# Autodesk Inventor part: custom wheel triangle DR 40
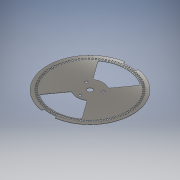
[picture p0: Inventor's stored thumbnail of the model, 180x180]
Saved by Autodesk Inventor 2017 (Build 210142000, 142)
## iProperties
Created: 2016-09
Part Number: custom wheel triangle DR 40
Material: Generic
Document SubType Name: Modeling
Designer: Radek
Density: 1 g/cm^3
Appearance: Mirror
Author: Radek
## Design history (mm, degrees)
workplane "Work Plane1"
sketch "Sketch1"
  geometry: L1 (-46.781, 4.422)-(-44.253, 4.183) reference; L2 (-44.362, 2.791)-(-46.897, 2.951) reference; L3 (-46.411, 7.351)-(-43.903, 6.954) reference; L4 (-44.099, 5.571)-(-46.619, 5.889) reference; L5 (-45.858, 10.251)-(-43.38, 9.696) reference; L6 (-43.663, 8.329)-(-46.158, 8.805) reference; L7 (-45.124, 13.11)-(-42.685, 12.401) reference; L8 (-43.054, 11.054)-(-45.514, 11.686) reference; L9 (-44.212, 15.917)-(-41.822, 15.057) reference; L10 (-42.274, 13.736)-(-44.69, 14.521) reference; L11 (-43.125, 18.662)-(-40.794, 17.653) reference; L12 (-41.329, 16.363)-(-43.69, 17.298) reference; L13 (-41.868, 21.333)-(-39.605, 20.18) reference; L14 (-40.22, 18.926)-(-42.518, 20.007) reference; L15 (-40.446, 23.92)-(-38.26, 22.627) reference; L16 (-38.952, 21.414)-(-41.178, 22.638) reference; L17 (-38.865, 26.412)-(-36.764, 24.985) reference; L18 (-37.53, 23.818)-(-39.675, 25.179) reference; L19 (-37.129, 28.801)-(-35.122, 27.244) reference; L20 (-35.961, 26.127)-(-38.016, 27.62) reference; L21 (-35.248, 31.075)-(-33.342, 29.395) reference; L22 (-34.249, 28.333)-(-36.206, 29.953) reference; L23 (-33.227, 33.227)-(-31.431, 31.431) reference; L24 (-32.403, 30.428)-(-34.254, 32.167) reference; L25 (-31.075, 35.248)-(-29.395, 33.342) reference; L26 (-30.428, 32.403)-(-32.167, 34.254) reference; L27 (-28.801, 37.129)-(-27.244, 35.122) reference; L28 (-28.333, 34.249)-(-29.953, 36.206) reference; L29 (-26.412, 38.865)-(-24.985, 36.764) reference; L30 (-26.127, 35.961)-(-27.62, 38.016) reference; L31 (-23.92, 40.446)-(-22.627, 38.26) reference; L32 (-23.818, 37.53)-(-25.179, 39.675) reference; L33 (-21.333, 41.868)-(-20.18, 39.605) reference; L34 (-21.414, 38.952)-(-22.638, 41.178) reference; L35 (-18.662, 43.125)-(-17.653, 40.794) reference; L36 (-18.926, 40.22)-(-20.007, 42.518) reference; L37 (-15.917, 44.212)-(-15.057, 41.822) reference; L38 (-16.363, 41.329)-(-17.298, 43.69) reference; L39 (-13.11, 45.124)-(-12.401, 42.685) reference; L40 (-13.736, 42.274)-(-14.521, 44.69) reference; L41 (-10.251, 45.858)-(-9.696, 43.38) reference; L42 (-11.054, 43.054)-(-11.686, 45.514) reference; L43 (-7.351, 46.411)-(-6.954, 43.903) reference; L44 (-8.329, 43.663)-(-8.805, 46.158) reference; L45 (-4.422, 46.781)-(-4.183, 44.253) reference; L46 (-5.571, 44.099)-(-5.889, 46.619) reference; L47 (-1.476, 46.967)-(-1.396, 44.428) reference; L48 (-2.791, 44.362)-(-2.951, 46.897) reference; L49 (1.476, 46.967)-(1.396, 44.428) reference; L50 (0, 44.45)-(0, 46.99) reference; L51 (4.422, 46.781)-(4.183, 44.253) reference; L52 (2.791, 44.362)-(2.951, 46.897) reference; L53 (7.351, 46.411)-(6.954, 43.903) reference; L54 (5.571, 44.099)-(5.889, 46.619) reference; L55 (10.251, 45.858)-(9.696, 43.38) reference; L56 (8.329, 43.663)-(8.805, 46.158) reference; L57 (13.11, 45.124)-(12.401, 42.685) reference; L58 (11.054, 43.054)-(11.686, 45.514) reference; L59 (15.917, 44.212)-(15.057, 41.822) reference; L60 (13.736, 42.274)-(14.521, 44.69) reference; L61 (18.662, 43.125)-(17.653, 40.794) reference; L62 (16.363, 41.329)-(17.298, 43.69) reference; L63 (21.333, 41.868)-(20.18, 39.605) reference; L64 (18.926, 40.22)-(20.007, 42.518) reference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; C1 r 50.8 at (0, 0) reference; C2 r 2.984 at (0, 0) reference; C3 r 1.524 at (0, 6.553) reference; C4 r 1.524 at (10.339, 5.969) reference; C5 r 2.984 at (0, 0) reference; C6 r 1.524 at (0, -11.938) reference; C7 r 1.524 at (-5.675, -3.277) reference; C8 r 1.524 at (-10.339, 5.969) reference; C9 r 1.524 at (5.675, -3.277) reference; C10 r 50.8 at (0, 0) reference; C11 r 1.524 at (-5.675, -3.277) reference; C12 r 1.524 at (-10.339, 5.969) reference; C13 r 1.524 at (0, 6.553) reference; C14 r 1.524 at (10.339, 5.969) reference; C15 r 1.524 at (5.675, -3.277) reference; C16 r 1.524 at (0, -11.938) reference; C17 r 2.984 at (0, 0) reference; A1 r 17.081 centre (0, 0) between (0, -17.081) and (17.081, 0) reference; A2 r 17.081 centre (0, 0) between (0, 17.081) and (-17.081, 0) reference; A3 r 43.18 centre (0, 0) between (0, 43.18) and (-43.18, 0) reference; A4 r 43.18 centre (0, 0) between (0, -43.18) and (43.18, 0) reference; A5 r 44.45 centre (0, 0) between (-44.253, 4.183) and (-44.362, 2.791) reference; A6 r 46.99 centre (0, 0) between (-46.781, 4.422) and (-46.897, 2.951) reference; A7 r 44.45 centre (0, 0) between (-43.903, 6.954) and (-44.099, 5.571) reference; A8 r 46.99 centre (0, 0) between (-46.411, 7.351) and (-46.619, 5.889) reference; A9 r 44.45 centre (0, 0) between (-43.38, 9.696) and (-43.663, 8.329) reference; A10 r 46.99 centre (0, 0) between (-45.858, 10.251) and (-46.158, 8.805) reference; A11 r 44.45 centre (0, 0) between (-42.685, 12.401) and (-43.054, 11.054) reference; A12 r 46.99 centre (0, 0) between (-45.124, 13.11) and (-45.514, 11.686) reference; A13 r 44.45 centre (0, 0) between (-41.822, 15.057) and (-42.274, 13.736) reference; A14 r 46.99 centre (0, 0) between (-44.212, 15.917) and (-44.69, 14.521) reference; A15 r 44.45 centre (0, 0) between (-40.794, 17.653) and (-41.329, 16.363) reference; A16 r 46.99 centre (0, 0) between (-43.125, 18.662) and (-43.69, 17.298) reference; A17 r 44.45 centre (0, 0) between (-39.605, 20.18) and (-40.22, 18.926) reference; A18 r 46.99 centre (0, 0) between (-41.868, 21.333) and (-42.518, 20.007) reference; A19 r 44.45 centre (0, 0) between (-38.26, 22.627) and (-38.952, 21.414) reference; A20 r 46.99 centre (0, 0) between (-40.446, 23.92) and (-41.178, 22.638) reference; A21 r 44.45 centre (0, 0) between (-36.764, 24.985) and (-37.53, 23.818) reference; A22 r 46.99 centre (0, 0) between (-38.865, 26.412) and (-39.675, 25.179) reference; A23 r 44.45 centre (0, 0) between (-35.122, 27.244) and (-35.961, 26.127) reference; A24 r 46.99 centre (0, 0) between (-37.129, 28.801) and (-38.016, 27.62) reference; A25 r 44.45 centre (0, 0) between (-33.342, 29.395) and (-34.249, 28.333) reference; A26 r 46.99 centre (0, 0) between (-35.248, 31.075) and (-36.206, 29.953) reference; A27 r 44.45 centre (0, 0) between (-31.431, 31.431) and (-32.403, 30.428) reference; A28 r 46.99 centre (0, 0) between (-33.227, 33.227) and (-34.254, 32.167) reference; A29 r 44.45 centre (0, 0) between (-29.395, 33.342) and (-30.428, 32.403) reference; A30 r 46.99 centre (0, 0) between (-31.075, 35.248) and (-32.167, 34.254) reference; A31 r 44.45 centre (0, 0) between (-27.244, 35.122) and (-28.333, 34.249) reference; A32 r 46.99 centre (0, 0) between (-28.801, 37.129) and (-29.953, 36.206) reference; A33 r 44.45 centre (0, 0) between (-24.985, 36.764) and (-26.127, 35.961) reference; A34 r 46.99 centre (0, 0) between (-26.412, 38.865) and (-27.62, 38.016) reference; A35 r 44.45 centre (0, 0) between (-22.627, 38.26) and (-23.818, 37.53) reference; A36 r 46.99 centre (0, 0) between (-23.92, 40.446) and (-25.179, 39.675) reference; A37 r 44.45 centre (0, 0) between (-20.18, 39.605) and (-21.414, 38.952) reference; A38 r 46.99 centre (0, 0) between (-21.333, 41.868) and (-22.638, 41.178) reference; A39 r 44.45 centre (0, 0) between (-17.653, 40.794) and (-18.926, 40.22) reference; A40 r 46.99 centre (0, 0) between (-18.662, 43.125) and (-20.007, 42.518) reference; A41 r 44.45 centre (0, 0) between (-15.057, 41.822) and (-16.363, 41.329) reference; A42 r 46.99 centre (0, 0) between (-15.917, 44.212) and (-17.298, 43.69) reference; A43 r 44.45 centre (0, 0) between (-12.401, 42.685) and (-13.736, 42.274) reference; A44 r 46.99 centre (0, 0) between (-13.11, 45.124) and (-14.521, 44.69) reference; A45 r 44.45 centre (0, 0) between (-9.696, 43.38) and (-11.054, 43.054) reference; A46 r 46.99 centre (0, 0) between (-10.251, 45.858) and (-11.686, 45.514) reference; A47 r 44.45 centre (0, 0) between (-6.954, 43.903) and (-8.329, 43.663) reference; A48 r 46.99 centre (0, 0) between (-7.351, 46.411) and (-8.805, 46.158) reference; A49 r 44.45 centre (0, 0) between (-4.183, 44.253) and (-5.571, 44.099) reference; A50 r 46.99 centre (0, 0) between (-4.422, 46.781) and (-5.889, 46.619) reference; A51 r 44.45 centre (0, 0) between (-1.396, 44.428) and (-2.791, 44.362) reference; A52 r 46.99 centre (0, 0) between (-1.476, 46.967) and (-2.951, 46.897) reference; A53 r 44.45 centre (0, 0) between (1.396, 44.428) and (0, 44.45) reference; A54 r 46.99 centre (0, 0) between (1.476, 46.967) and (0, 46.99) reference; A55 r 44.45 centre (0, 0) between (4.183, 44.253) and (2.791, 44.362) reference; A56 r 46.99 centre (0, 0) between (4.422, 46.781) and (2.951, 46.897) reference; A57 r 44.45 centre (0, 0) between (6.954, 43.903) and (5.571, 44.099) reference; A58 r 46.99 centre (0, 0) between (7.351, 46.411) and (5.889, 46.619) reference; A59 r 44.45 centre (0, 0) between (9.696, 43.38) and (8.329, 43.663) reference; A60 r 46.99 centre (0, 0) between (10.251, 45.858) and (8.805, 46.158) reference; A61 r 44.45 centre (0, 0) between (12.401, 42.685) and (11.054, 43.054) reference; A62 r 46.99 centre (0, 0) between (13.11, 45.124) and (11.686, 45.514) reference; A63 r 44.45 centre (0, 0) between (15.057, 41.822) and (13.736, 42.274) reference; A64 r 46.99 centre (0, 0) between (15.917, 44.212) and (14.521, 44.69) reference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; 1 further point
  constraints: 8 end point, 2 collinear, 1 parallel
extrude "Extrusion2" new body sketch "Sketch1" distance "d2" = 0.3; taper "d3" = 0 deg
sketch "Sketch2"
  geometry: L1 (-46.781, 4.422)-(-44.253, 4.183) reference; L2 (-44.362, 2.791)-(-46.897, 2.951) reference; L3 (-46.411, 7.351)-(-43.903, 6.954) reference; L4 (-44.099, 5.571)-(-46.619, 5.889) reference; L5 (-45.858, 10.251)-(-43.38, 9.696) reference; L6 (-43.663, 8.329)-(-46.158, 8.805) reference; L7 (-45.124, 13.11)-(-42.685, 12.401) reference; L8 (-43.054, 11.054)-(-45.514, 11.686) reference; L9 (-44.212, 15.917)-(-41.822, 15.057) reference; L10 (-42.274, 13.736)-(-44.69, 14.521) reference; L11 (-43.125, 18.662)-(-40.794, 17.653) reference; L12 (-41.329, 16.363)-(-43.69, 17.298) reference; L13 (-41.868, 21.333)-(-39.605, 20.18) reference; L14 (-40.22, 18.926)-(-42.518, 20.007) reference; L15 (-40.446, 23.92)-(-38.26, 22.627) reference; L16 (-38.952, 21.414)-(-41.178, 22.638) reference; L17 (-38.865, 26.412)-(-36.764, 24.985) reference; L18 (-37.53, 23.818)-(-39.675, 25.179) reference; L19 (-37.129, 28.801)-(-35.122, 27.244) reference; L20 (-35.961, 26.127)-(-38.016, 27.62) reference; L21 (-35.248, 31.075)-(-33.342, 29.395) reference; L22 (-34.249, 28.333)-(-36.206, 29.953) reference; L23 (-33.227, 33.227)-(-31.431, 31.431) reference; L24 (-32.403, 30.428)-(-34.254, 32.167) reference; L25 (-31.075, 35.248)-(-29.395, 33.342) reference; L26 (-30.428, 32.403)-(-32.167, 34.254) reference; L27 (-28.801, 37.129)-(-27.244, 35.122) reference; L28 (-28.333, 34.249)-(-29.953, 36.206) reference; L29 (-26.412, 38.865)-(-24.985, 36.764) reference; L30 (-26.127, 35.961)-(-27.62, 38.016) reference; L31 (-23.92, 40.446)-(-22.627, 38.26) reference; L32 (-23.818, 37.53)-(-25.179, 39.675) reference; L33 (-21.333, 41.868)-(-20.18, 39.605) reference; L34 (-21.414, 38.952)-(-22.638, 41.178) reference; L35 (-18.662, 43.125)-(-17.653, 40.794) reference; L36 (-18.926, 40.22)-(-20.007, 42.518) reference; L37 (-15.917, 44.212)-(-15.057, 41.822) reference; L38 (-16.363, 41.329)-(-17.298, 43.69) reference; L39 (-13.11, 45.124)-(-12.401, 42.685) reference; L40 (-13.736, 42.274)-(-14.521, 44.69) reference; L41 (-10.251, 45.858)-(-9.696, 43.38) reference; L42 (-11.054, 43.054)-(-11.686, 45.514) reference; L43 (-7.351, 46.411)-(-6.954, 43.903) reference; L44 (-8.329, 43.663)-(-8.805, 46.158) reference; L45 (-4.422, 46.781)-(-4.183, 44.253) reference; L46 (-5.571, 44.099)-(-5.889, 46.619) reference; L47 (-1.476, 46.967)-(-1.396, 44.428) reference; L48 (-2.791, 44.362)-(-2.951, 46.897) reference; L49 (1.476, 46.967)-(1.396, 44.428) reference; L50 (0, 44.45)-(0, 46.99) reference; L51 (4.422, 46.781)-(4.183, 44.253) reference; L52 (2.791, 44.362)-(2.951, 46.897) reference; L53 (7.351, 46.411)-(6.954, 43.903) reference; L54 (5.571, 44.099)-(5.889, 46.619) reference; L55 (10.251, 45.858)-(9.696, 43.38) reference; L56 (8.329, 43.663)-(8.805, 46.158) reference; L57 (13.11, 45.124)-(12.401, 42.685) reference; L58 (11.054, 43.054)-(11.686, 45.514) reference; L59 (15.917, 44.212)-(15.057, 41.822) reference; L60 (13.736, 42.274)-(14.521, 44.69) reference; L61 (18.662, 43.125)-(17.653, 40.794) reference; L62 (16.363, 41.329)-(17.298, 43.69) reference; L63 (21.333, 41.868)-(20.18, 39.605) reference; L64 (18.926, 40.22)-(20.007, 42.518) reference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; C1 r 50.8 at (0, 0) reference; C2 r 1.524 at (-5.675, -3.277) reference; C3 r 1.524 at (-10.339, 5.969) reference; C4 r 1.524 at (0, 6.553) reference; C5 r 1.524 at (10.339, 5.969) reference; C6 r 1.524 at (5.675, -3.277) reference; C7 r 1.524 at (0, -11.938) reference; C8 r 2.984 at (0, 0) reference; A1 r 44.45 centre (0, 0) between (-44.253, 4.183) and (-44.362, 2.791) reference; A2 r 46.99 centre (0, 0) between (-46.781, 4.422) and (-46.897, 2.951) reference; A3 r 44.45 centre (0, 0) between (-43.903, 6.954) and (-44.099, 5.571) reference; A4 r 46.99 centre (0, 0) between (-46.411, 7.351) and (-46.619, 5.889) reference; A5 r 44.45 centre (0, 0) between (-43.38, 9.696) and (-43.663, 8.329) reference; A6 r 46.99 centre (0, 0) between (-45.858, 10.251) and (-46.158, 8.805) reference; A7 r 44.45 centre (0, 0) between (-42.685, 12.401) and (-43.054, 11.054) reference; A8 r 46.99 centre (0, 0) between (-45.124, 13.11) and (-45.514, 11.686) reference; A9 r 44.45 centre (0, 0) between (-41.822, 15.057) and (-42.274, 13.736) reference; A10 r 46.99 centre (0, 0) between (-44.212, 15.917) and (-44.69, 14.521) reference; A11 r 44.45 centre (0, 0) between (-40.794, 17.653) and (-41.329, 16.363) reference; A12 r 46.99 centre (0, 0) between (-43.125, 18.662) and (-43.69, 17.298) reference; A13 r 44.45 centre (0, 0) between (-39.605, 20.18) and (-40.22, 18.926) reference; A14 r 46.99 centre (0, 0) between (-41.868, 21.333) and (-42.518, 20.007) reference; A15 r 44.45 centre (0, 0) between (-38.26, 22.627) and (-38.952, 21.414) reference; A16 r 46.99 centre (0, 0) between (-40.446, 23.92) and (-41.178, 22.638) reference; A17 r 44.45 centre (0, 0) between (-36.764, 24.985) and (-37.53, 23.818) reference; A18 r 46.99 centre (0, 0) between (-38.865, 26.412) and (-39.675, 25.179) reference; A19 r 44.45 centre (0, 0) between (-35.122, 27.244) and (-35.961, 26.127) reference; A20 r 46.99 centre (0, 0) between (-37.129, 28.801) and (-38.016, 27.62) reference; A21 r 44.45 centre (0, 0) between (-33.342, 29.395) and (-34.249, 28.333) reference; A22 r 46.99 centre (0, 0) between (-35.248, 31.075) and (-36.206, 29.953) reference; A23 r 44.45 centre (0, 0) between (-31.431, 31.431) and (-32.403, 30.428) reference; A24 r 46.99 centre (0, 0) between (-33.227, 33.227) and (-34.254, 32.167) reference; A25 r 44.45 centre (0, 0) between (-29.395, 33.342) and (-30.428, 32.403) reference; A26 r 46.99 centre (0, 0) between (-31.075, 35.248) and (-32.167, 34.254) reference; A27 r 44.45 centre (0, 0) between (-27.244, 35.122) and (-28.333, 34.249) reference; A28 r 46.99 centre (0, 0) between (-28.801, 37.129) and (-29.953, 36.206) reference; A29 r 44.45 centre (0, 0) between (-24.985, 36.764) and (-26.127, 35.961) reference; A30 r 46.99 centre (0, 0) between (-26.412, 38.865) and (-27.62, 38.016) reference; A31 r 44.45 centre (0, 0) between (-22.627, 38.26) and (-23.818, 37.53) reference; A32 r 46.99 centre (0, 0) between (-23.92, 40.446) and (-25.179, 39.675) reference; A33 r 44.45 centre (0, 0) between (-20.18, 39.605) and (-21.414, 38.952) reference; A34 r 46.99 centre (0, 0) between (-21.333, 41.868) and (-22.638, 41.178) reference; A35 r 44.45 centre (0, 0) between (-17.653, 40.794) and (-18.926, 40.22) reference; A36 r 46.99 centre (0, 0) between (-18.662, 43.125) and (-20.007, 42.518) reference; A37 r 44.45 centre (0, 0) between (-15.057, 41.822) and (-16.363, 41.329) reference; A38 r 46.99 centre (0, 0) between (-15.917, 44.212) and (-17.298, 43.69) reference; A39 r 44.45 centre (0, 0) between (-12.401, 42.685) and (-13.736, 42.274) reference; A40 r 46.99 centre (0, 0) between (-13.11, 45.124) and (-14.521, 44.69) reference; A41 r 44.45 centre (0, 0) between (-9.696, 43.38) and (-11.054, 43.054) reference; A42 r 46.99 centre (0, 0) between (-10.251, 45.858) and (-11.686, 45.514) reference; A43 r 44.45 centre (0, 0) between (-6.954, 43.903) and (-8.329, 43.663) reference; A44 r 46.99 centre (0, 0) between (-7.351, 46.411) and (-8.805, 46.158) reference; A45 r 44.45 centre (0, 0) between (-4.183, 44.253) and (-5.571, 44.099) reference; A46 r 46.99 centre (0, 0) between (-4.422, 46.781) and (-5.889, 46.619) reference; A47 r 44.45 centre (0, 0) between (-1.396, 44.428) and (-2.791, 44.362) reference; A48 r 46.99 centre (0, 0) between (-1.476, 46.967) and (-2.951, 46.897) reference; A49 r 44.45 centre (0, 0) between (1.396, 44.428) and (0, 44.45) reference; A50 r 46.99 centre (0, 0) between (1.476, 46.967) and (0, 46.99) reference; A51 r 44.45 centre (0, 0) between (4.183, 44.253) and (2.791, 44.362) reference; A52 r 46.99 centre (0, 0) between (4.422, 46.781) and (2.951, 46.897) reference; A53 r 44.45 centre (0, 0) between (6.954, 43.903) and (5.571, 44.099) reference; A54 r 46.99 centre (0, 0) between (7.351, 46.411) and (5.889, 46.619) reference; A55 r 44.45 centre (0, 0) between (9.696, 43.38) and (8.329, 43.663) reference; A56 r 46.99 centre (0, 0) between (10.251, 45.858) and (8.805, 46.158) reference; A57 r 44.45 centre (0, 0) between (12.401, 42.685) and (11.054, 43.054) reference; A58 r 46.99 centre (0, 0) between (13.11, 45.124) and (11.686, 45.514) reference; A59 r 44.45 centre (0, 0) between (15.057, 41.822) and (13.736, 42.274) reference; A60 r 46.99 centre (0, 0) between (15.917, 44.212) and (14.521, 44.69) reference; A61 r 44.45 centre (0, 0) between (17.653, 40.794) and (16.363, 41.329) reference; A62 r 46.99 centre (0, 0) between (18.662, 43.125) and (17.298, 43.69) reference; A63 r 44.45 centre (0, 0) between (20.18, 39.605) and (18.926, 40.22) reference; A64 r 46.99 centre (0, 0) between (21.333, 41.868) and (20.007, 42.518) reference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; 1 further point
  constraints: 8 end point, 1 collinear
extrude "Extrusion3" cut sketch "Sketch2" stored distance "d4" = 0.254; taper "d5" = 0 deg
sketch "Sketch3" dims "d20" = 9.26667 (= 0.5 x holediameter), "d21" = 13.10505 (= 1.41421 x d20)
  geometry: L1 (-10.339, 5.969)-(10.339, 5.969); L2 (0, 0)-(50.8, 0); L3 (0, 44.45)-(0, 46.99) reference; L4 (0, 0)-(0, 50.8); L5 (0, 30)-(0, 16.895); L6 (0, 50.165)-(0, 48.26) reference; L7 (-48.26, 0)-(-50.165, 0) reference; L8 (0, 0)-(24.135, 24.418); L9 (0, 50.8)-(0, 50.165); L10 (7.33, 15.222)-(18.703, 38.836); L11 (-7.33, 15.222)-(-18.703, 38.836); C1 r 2.984 at (0, 0) reference; C2 r 15.25 at (0, 0); C3 r 1.524 at (-10.339, 5.969) reference; C4 r 1.524 at (0, -11.938) reference; C5 r 1.524 at (10.339, 5.969) reference; C6 r 1.524 at (-5.675, -3.277) reference; C7 r 1.524 at (5.675, -3.277) reference; A1 r 50.8 centre (0, 0) between (50.8, 0) and (0, 50.8) reference; A2 r 48.26 centre (0, 0) between (0, 48.26) and (-48.26, 0) reference; A3 r 50.165 centre (0, 0) between (0, 50.165) and (-50.165, 0) reference; A4 r 50.165 centre (0, 0) between (-20.154, -45.939) and (22.037, -45.066); A5 r 48.26 centre (0, 0) between (-19.033, -44.348) and (20.956, -43.472); 3 further points; 3 other entities
  constraints: 16 end point, 8 point on circle, 3 centre point, 3 coincident, 2 midpoint, 2 vertical, 1 collinear, 1 horizontal, 1 parallel, 1 point on line, 1 vertical alignment, 19 other
  dimensions: "d9" = 30.5 diameter of C2; "d18" = 0 distance between parallel lines of L4 L5; "d19" = 30 distance of point (0, 0) L5.start (= offaxis); "d24" = 4.48799 dimension on point (0, 0) L5.start point (-13.017, 27.029) (= 0.5 x angle); "d28" = 4.48799 dimension on point (0, 0) point (13.017, 27.029) L5.start (= 0.5 x angle); "d32" = 0.635 distance of L4.end L6.start (derived)
extrude "Extrusion7" cut sketch "Sketch3" stored distance "d40" = 10; taper "d41" = 0 deg
sketch "Sketch4"
  geometry: L1 (-3.221, 42.985)-(-1.263, 16.848) reference; L2 (1.263, 16.848)-(3.221, 42.985) reference; L3 (3.221, 42.985)-(1.263, 16.848) reference; L4 (-1.263, 16.848)-(-3.221, 42.985) reference; L5 (-1.263, 16.848)-(-3.221, 42.985); L6 (1.263, 16.848)-(3.221, 42.985); C1 r 2.984 at (0, 0) reference; C2 r 50.8 at (0, 0) reference; A1 r 16.895 centre (0, 0) between (1.263, 16.848) and (-1.263, 16.848); A2 r 43.105 centre (0, 0) between (3.221, 42.985) and (-3.221, 42.985); 3 further points; 2 other entities
  constraints: 4 end point, 4 point on circle, 2 centre point, 2 coincident, 2 collinear, 2 other
extrude "Extrusion8" cut sketch "Sketch4" stored distance "d42" = 10; taper "d43" = 0 deg
sketch "Sketch5"
  geometry: L1 (0, 0)-(-7.947, 50.175); L2 (0, 0)-(7.947, 50.175); L3 (7.524, 47.508)-(7.837, 49.483); L4 (-7.524, 47.508)-(-7.837, 49.483); L5 (6.954, 43.903)-(7.351, 46.411) reference; L6 (4.422, 46.781)-(4.183, 44.253) reference; L7 (7.351, 46.411)-(6.954, 43.903) reference; C1 r 2.984 at (0, 0) reference; A1 r 50.8 centre (0, 0) between (-7.947, 50.175) and (7.947, 50.175) reference; A2 r 16.895 centre (0, 0) between (1.263, 16.848) and (-1.263, 16.848) reference; A3 r 43.105 centre (0, 0) between (3.221, 42.985) and (-3.221, 42.985) reference; A4 r 48.1 centre (0, 0) between (7.524, 47.508) and (-7.524, 47.508); A5 r 50.1 centre (0, 0) between (7.837, 49.483) and (-7.837, 49.483); 4 further points; 2 other entities
  constraints: 8 end point, 6 point on circle, 3 point on line, 2 centre point, 2 coincident, 2 collinear, 1 midpoint, 8 other
  dimensions: "d44" = 0.7 radial gap between concentric circles of A1 A5; "d45" = 2 radial gap between concentric circles of A5 A4; "d53" = 18 deg angle of L1 L2
extrude "Extrusion9" cut sketch "Sketch5" stored distance "d46" = 10; taper "d47" = 0 deg
pattern_circular "Circular Pattern3" dims angle "d49" = 360 deg
sketch "Sketch6"
  geometry: L1 (16.895, 0)-(16.848, 0) reference; L2 (42.985, 0)-(43.105, 0) reference; L3 (16.848, -0.3)-(16.895, -0.3) reference; L4 (43.105, -0.3)-(42.985, -0.3) reference; L5 (-50.8, 0)-(50.8, 0) reference; L6 (-50.8, -0.3)-(50.8, -0.3) reference; L7 (16.895, 0)-(43.105, 0); L8 (16.895, -0.3)-(43.105, -0.3); L9 (30, -0.3)-(30, 0); L10 (30, -0.15)-(32.935, -3.085); 1 further point
  constraints: 8 end point, 3 midpoint, 1 collinear, 1 parallel
  dimensions: "d51" = 135 deg angle of L10 L9
workaxis "Work Axis1"
workplane "Work Plane3"
  workplane "Work Plane2"
sketch "Sketch7"
  geometry: L1 (0, -11.938)-(-10.339, 5.969); C1 r 1.524 at (0, -11.938) reference; C2 r 1.524 at (-10.339, 5.969) reference; C3 r 2.984 at (0, 0) reference; C4 r 10.414 at (0, 0); 2 further points
  constraints: 2 end point, 1 centre point, 1 coincident, 1 tangent, 1 other
extrude "Extrusion11" cut sketch "Sketch7" stored distance "d57" = 10; taper "d58" = 0 deg
sketch "Sketch8"
  geometry: L1 (7.837, 49.483)-(7.524, 47.508) reference; L2 (-7.524, 47.508)-(-7.837, 49.483) reference; L3 (-46.967, -1.476)-(-44.428, -1.396) reference; L4 (-44.428, -1.396)-(-44.362, -2.791) reference; L5 (-44.362, -2.791)-(-46.897, -2.951) reference; L6 (-46.897, -2.951)-(-46.967, -1.476) reference; L7 (-46.781, -4.422)-(-44.253, -4.183) reference; L8 (-44.253, -4.183)-(-44.099, -5.571) reference; L9 (-44.099, -5.571)-(-46.619, -5.889) reference; L10 (-46.619, -5.889)-(-46.781, -4.422) reference; L11 (-46.411, -7.351)-(-43.903, -6.954) reference; L12 (-43.903, -6.954)-(-43.663, -8.329) reference; L13 (-43.663, -8.329)-(-46.158, -8.805) reference; L14 (-46.158, -8.805)-(-46.411, -7.351) reference; L15 (-45.858, -10.251)-(-43.38, -9.696) reference; L16 (-43.38, -9.696)-(-43.054, -11.054) reference; L17 (-43.054, -11.054)-(-45.514, -11.686) reference; L18 (-45.514, -11.686)-(-45.858, -10.251) reference; L19 (-45.124, -13.11)-(-42.685, -12.401) reference; L20 (-42.685, -12.401)-(-42.274, -13.736) reference; L21 (-42.274, -13.736)-(-44.69, -14.521) reference; L22 (-44.69, -14.521)-(-45.124, -13.11) reference; L23 (-44.212, -15.917)-(-41.822, -15.057) reference; L24 (-41.822, -15.057)-(-41.329, -16.363) reference; L25 (-41.329, -16.363)-(-43.69, -17.298) reference; L26 (-43.69, -17.298)-(-44.212, -15.917) reference; L27 (-43.125, -18.662)-(-40.794, -17.653) reference; L28 (-40.794, -17.653)-(-40.22, -18.926) reference; L29 (-40.22, -18.926)-(-42.518, -20.007) reference; L30 (-42.518, -20.007)-(-43.125, -18.662) reference; L31 (-41.868, -21.333)-(-39.605, -20.18) reference; L32 (-39.605, -20.18)-(-38.952, -21.414) reference; L33 (-38.952, -21.414)-(-41.178, -22.638) reference; L34 (-41.178, -22.638)-(-41.868, -21.333) reference; L35 (-40.446, -23.92)-(-38.26, -22.627) reference; L36 (-38.26, -22.627)-(-37.53, -23.818) reference; L37 (-37.53, -23.818)-(-39.675, -25.179) reference; L38 (-39.675, -25.179)-(-40.446, -23.92) reference; L39 (-38.865, -26.412)-(-36.764, -24.985) reference; L40 (-36.764, -24.985)-(-35.961, -26.127) reference; L41 (-35.961, -26.127)-(-38.016, -27.62) reference; L42 (-38.016, -27.62)-(-38.865, -26.412) reference; L43 (-37.129, -28.801)-(-35.122, -27.244) reference; L44 (-35.122, -27.244)-(-34.249, -28.333) reference; L45 (-34.249, -28.333)-(-36.206, -29.953) reference; L46 (-36.206, -29.953)-(-37.129, -28.801) reference; L47 (-35.248, -31.075)-(-33.342, -29.395) reference; L48 (-33.342, -29.395)-(-32.403, -30.428) reference; L49 (-32.403, -30.428)-(-34.254, -32.167) reference; L50 (-34.254, -32.167)-(-35.248, -31.075) reference; L51 (-33.227, -33.227)-(-31.431, -31.431) reference; L52 (-31.431, -31.431)-(-30.428, -32.403) reference; L53 (-30.428, -32.403)-(-32.167, -34.254) reference; L54 (-32.167, -34.254)-(-33.227, -33.227) reference; L55 (-31.075, -35.248)-(-29.395, -33.342) reference; L56 (-29.395, -33.342)-(-28.333, -34.249) reference; L57 (-28.333, -34.249)-(-29.953, -36.206) reference; L58 (-29.953, -36.206)-(-31.075, -35.248) reference; L59 (-28.801, -37.129)-(-27.244, -35.122) reference; L60 (-27.244, -35.122)-(-26.127, -35.961) reference; L61 (-26.127, -35.961)-(-27.62, -38.016) reference; L62 (-27.62, -38.016)-(-28.801, -37.129) reference; L63 (-26.412, -38.865)-(-24.985, -36.764) reference; L64 (-24.985, -36.764)-(-23.818, -37.53) reference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; C1 r 2.984 at (0, 0) reference; C2 r 1.524 at (5.675, -3.277) reference; C3 r 1.524 at (-10.339, 5.969) reference; C4 r 1.524 at (-5.675, -3.277) reference; C5 r 1.524 at (0, -11.938) reference; C6 r 1.524 at (10.339, 5.969) reference; C7 r 1.524 at (0, 6.553) reference; C8 r 50.8 at (0, 0) reference; C9 r 2.984 at (0, 0) reference; A1 r 48.1 centre (0, 0) between (7.524, 47.508) and (-7.524, 47.508) reference; A2 r 50.1 centre (0, 0) between (7.837, 49.483) and (-7.837, 49.483) reference; A3 r 43.105 centre (0, 0) between (3.221, 42.985) and (-3.221, 42.985) reference; A4 r 16.895 centre (0, 0) between (1.263, 16.848) and (-1.263, 16.848) reference; A5 r 43.105 centre (0, 0) between (-3.221, -42.985) and (3.221, -42.985); A6 r 16.895 centre (0, 0) between (-1.263, -16.848) and (1.263, -16.848); 3 further points; 1 other entity
  constraints: 8 end point, 4 point on circle, 2 centre point, 2 coincident, 2 collinear, 2 point on line, 2 other
extrude "Extrusion12" cut sketch "Sketch8" stored distance "d59" = 10; taper "d60" = 0 deg
pattern_circular "Circular Pattern4" dims angle "d62" = 360 deg
sketch "Sketch9"
  geometry: L1 (-44.45, 0)-(-46.99, 0) reference; L2 (-46.99, 0)-(-46.967, 1.476) reference; L3 (-46.967, 1.476)-(-44.428, 1.396) reference; L4 (-44.428, 1.396)-(-44.45, 0) reference; L5 (-46.781, 4.422)-(-44.253, 4.183) reference; L6 (-44.253, 4.183)-(-44.362, 2.791) reference; L7 (-44.362, 2.791)-(-46.897, 2.951) reference; L8 (-46.897, 2.951)-(-46.781, 4.422) reference; L9 (-46.411, 7.351)-(-43.903, 6.954) reference; L10 (-43.903, 6.954)-(-44.099, 5.571) reference; L11 (-44.099, 5.571)-(-46.619, 5.889) reference; L12 (-46.619, 5.889)-(-46.411, 7.351) reference; L13 (-45.858, 10.251)-(-43.38, 9.696) reference; L14 (-43.38, 9.696)-(-43.663, 8.329) reference; L15 (-43.663, 8.329)-(-46.158, 8.805) reference; L16 (-46.158, 8.805)-(-45.858, 10.251) reference; L17 (-45.124, 13.11)-(-42.685, 12.401) reference; L18 (-42.685, 12.401)-(-43.054, 11.054) reference; L19 (-43.054, 11.054)-(-45.514, 11.686) reference; L20 (-45.514, 11.686)-(-45.124, 13.11) reference; L21 (-44.212, 15.917)-(-41.822, 15.057) reference; L22 (-41.822, 15.057)-(-42.274, 13.736) reference; L23 (-42.274, 13.736)-(-44.69, 14.521) reference; L24 (-44.69, 14.521)-(-44.212, 15.917) reference; L25 (-43.125, 18.662)-(-40.794, 17.653) reference; L26 (-40.794, 17.653)-(-41.329, 16.363) reference; L27 (-41.329, 16.363)-(-43.69, 17.298) reference; L28 (-43.69, 17.298)-(-43.125, 18.662) reference; L29 (-41.868, 21.333)-(-39.605, 20.18) reference; L30 (-39.605, 20.18)-(-40.22, 18.926) reference; L31 (-40.22, 18.926)-(-42.518, 20.007) reference; L32 (-42.518, 20.007)-(-41.868, 21.333) reference; L33 (-40.446, 23.92)-(-38.26, 22.627) reference; L34 (-38.26, 22.627)-(-38.952, 21.414) reference; L35 (-38.952, 21.414)-(-41.178, 22.638) reference; L36 (-41.178, 22.638)-(-40.446, 23.92) reference; L37 (-38.865, 26.412)-(-36.764, 24.985) reference; L38 (-36.764, 24.985)-(-37.53, 23.818) reference; L39 (-37.53, 23.818)-(-39.675, 25.179) reference; L40 (-39.675, 25.179)-(-38.865, 26.412) reference; L41 (-37.129, 28.801)-(-35.122, 27.244) reference; L42 (-35.122, 27.244)-(-35.961, 26.127) reference; L43 (-35.961, 26.127)-(-38.016, 27.62) reference; L44 (-38.016, 27.62)-(-37.129, 28.801) reference; L45 (-35.248, 31.075)-(-33.342, 29.395) reference; L46 (-33.342, 29.395)-(-34.249, 28.333) reference; L47 (-34.249, 28.333)-(-36.206, 29.953) reference; L48 (-36.206, 29.953)-(-35.248, 31.075) reference; L49 (-33.227, 33.227)-(-31.431, 31.431) reference; L50 (-31.431, 31.431)-(-32.403, 30.428) reference; L51 (-32.403, 30.428)-(-34.254, 32.167) reference; L52 (-34.254, 32.167)-(-33.227, 33.227) reference; L53 (-31.075, 35.248)-(-29.395, 33.342) reference; L54 (-29.395, 33.342)-(-30.428, 32.403) reference; L55 (-30.428, 32.403)-(-32.167, 34.254) reference; L56 (-32.167, 34.254)-(-31.075, 35.248) reference; L57 (-28.801, 37.129)-(-27.244, 35.122) reference; L58 (-27.244, 35.122)-(-28.333, 34.249) reference; L59 (-28.333, 34.249)-(-29.953, 36.206) reference; L60 (-29.953, 36.206)-(-28.801, 37.129) reference; L61 (-26.412, 38.865)-(-24.985, 36.764) reference; L62 (-24.985, 36.764)-(-26.127, 35.961) reference; L63 (-26.127, 35.961)-(-27.62, 38.016) reference; L64 (-27.62, 38.016)-(-26.412, 38.865) reference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; C1 r 50.8 at (0, 0) reference; C2 r 1.524 at (0, 6.553) reference; C3 r 1.524 at (10.339, 5.969) reference; C4 r 1.524 at (0, -11.938) reference; C5 r 1.524 at (-5.675, -3.277) reference; C6 r 1.524 at (-10.339, 5.969) reference; C7 r 1.524 at (5.675, -3.277) reference; C8 r 2.984 at (0, 0) reference; C9 r 2.984 at (0, 0) reference; A1 r 16.895 centre (0, 0) between (1.263, 16.848) and (-1.263, 16.848) reference; A2 r 48.1 centre (0, 0) between (7.524, 47.508) and (-7.524, 47.508) reference; A3 r 50.1 centre (0, 0) between (7.837, 49.483) and (-7.837, 49.483) reference; A4 r 48.1 centre (0, 0) between (-7.524, -47.508) and (7.524, -47.508); A5 r 55.8 centre (0, 0) between (-8.729, -55.113) and (8.729, -55.113); A6 r 43.105 centre (0, 0) between (3.221, 42.985) and (-3.221, 42.985) reference; 2 further points
  constraints: 8 end point, 4 point on circle, 4 point on line, 2 centre point, 2 coincident, 2 collinear
  dimensions: "d64" = 5 radial gap between concentric circles of C1 A5
extrude "Extrusion13" cut sketch "Sketch9" stored distance "d65" = 10; taper "d66" = 0 deg
pattern_circular "Circular Pattern5" dims angle "d68" = 360 deg
fillet "Fillet1" dims "d70" = 0.5 (derived)
fillet "Fillet3" dims "d72" = 0.5 (derived)
pattern_circular "Circular Pattern7" dims angle "d77" = 360 deg
sketch "Sketch10"
  geometry: C1 r 1.524 at (-5.675, -3.277) reference; C2 r 1.524 at (0, 6.553) reference; C3 r 1.524 at (5.675, -3.277) reference; 1 further point
extrude "Extrusion14" join sketch "Sketch10" stored distance "d79" = 10; taper "d80" = 0 deg
sketch "Sketch11"
  geometry: L1 (7.868, 49.678)-(7.602, 47.999) reference; L2 (-7.602, 47.999)-(-7.868, 49.678) reference; L3 (-7.868, -49.678)-(-7.602, -47.999) reference; L4 (7.602, -47.999)-(7.868, -49.678) reference; L5 (-44.942, 0)-(-46.482, 0) reference; L6 (-46.982, 0.508)-(-46.975, 0.968) reference; L7 (-46.459, 1.46)-(-44.92, 1.412) reference; L8 (-44.436, 0.904)-(-44.442, 0.492) reference; L9 (-46.276, 4.374)-(-44.743, 4.229) reference; L10 (-44.291, 3.692)-(-44.324, 3.282) reference; L11 (-44.854, 2.822)-(-46.39, 2.919) reference; L12 (-46.857, 3.457)-(-46.821, 3.916) reference; L13 (-45.91, 7.271)-(-44.389, 7.031) reference; L14 (-43.972, 6.466)-(-44.03, 6.058) reference; L15 (-44.588, 5.633)-(-46.116, 5.826) reference; L16 (-46.548, 6.392)-(-46.483, 6.848) reference; L17 (-45.363, 10.14)-(-43.86, 9.804) reference; L18 (-43.479, 9.214)-(-43.563, 8.811) reference; L19 (-44.146, 8.421)-(-45.659, 8.71) reference; L20 (-46.055, 9.302)-(-45.961, 9.753) reference; L21 (-44.636, 12.968)-(-43.158, 12.538) reference; L22 (-42.815, 11.926)-(-42.924, 11.529) reference; L23 (-43.53, 11.177)-(-45.022, 11.56) reference; L24 (-45.38, 12.176)-(-45.258, 12.62) reference; L25 (-43.734, 15.745)-(-42.285, 15.224) reference; L26 (-41.982, 14.591)-(-42.115, 14.201) reference; L27 (-42.743, 13.888)-(-44.207, 14.364) reference; L28 (-44.526, 15.001)-(-44.377, 15.437) reference; L29 (-42.659, 18.46)-(-41.246, 17.849) reference; L30 (-40.983, 17.198)-(-41.14, 16.818) reference; L31 (-41.786, 16.544)-(-43.218, 17.111) reference; L32 (-43.496, 17.767)-(-43.32, 18.193) reference; L33 (-41.416, 21.102)-(-40.044, 20.403) reference; L34 (-39.822, 19.738)-(-40.003, 19.368) reference; L35 (-40.665, 19.135)-(-42.058, 19.791) reference; L36 (-42.294, 20.463)-(-42.092, 20.877) reference; L37 (-40.009, 23.661)-(-38.684, 22.877) reference; L38 (-38.504, 22.199)-(-38.708, 21.841) reference; L39 (-39.383, 21.651)-(-40.733, 22.393) reference; L40 (-40.926, 23.079)-(-40.698, 23.479) reference; L41 (-38.444, 26.127)-(-37.171, 25.261) reference; L42 (-37.034, 24.573)-(-37.26, 24.229) reference; L43 (-37.946, 24.081)-(-39.246, 24.906) reference; L44 (-39.396, 25.603)-(-39.143, 25.988) reference; L45 (-36.728, 28.489)-(-35.511, 27.545) reference; L46 (-35.418, 26.85)-(-35.665, 26.521) reference; L47 (-36.359, 26.416)-(-37.605, 27.321) reference; L48 (-37.711, 28.026)-(-37.434, 28.394) reference; L49 (-34.867, 30.739)-(-33.712, 29.721) reference; L50 (-33.662, 29.021)-(-33.93, 28.708) reference; L51 (-34.629, 28.647)-(-35.815, 29.629) reference; L52 (-35.877, 30.339)-(-35.578, 30.689) reference; L53 (-32.868, 32.868)-(-31.779, 31.779) reference; L54 (-31.773, 31.077)-(-32.06, 30.782) reference; L55 (-32.761, 30.765)-(-33.884, 31.819) reference; L56 (-33.901, 32.532)-(-33.58, 32.862) reference; L57 (-30.739, 34.867)-(-29.721, 33.712) reference; L58 (-29.759, 33.011)-(-30.064, 32.734) reference; L59 (-30.765, 32.761)-(-31.819, 33.884) reference; L60 (-31.791, 34.596)-(-31.451, 34.906) reference; L61 (-28.489, 36.728)-(-27.545, 35.511) reference; L62 (-27.628, 34.815)-(-27.949, 34.557) reference; L63 (-28.647, 34.629)-(-29.629, 35.815) reference; L64 (-29.556, 36.524)-(-29.197, 36.812) reference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; C1 r 1.524 at (10.339, 5.969) reference; C2 r 1.524 at (0, -11.938) reference; C3 r 1.524 at (-10.339, 5.969) reference; C4 r 2.984 at (0, 0) reference; C5 r 2.984 at (0, 0) reference; A1 r 0.5 centre (8.362, 49.6) between (8.445, 50.093) and (7.868, 49.678) reference; A2 r 48.1 centre (0, 0) between (7.035, 47.583) and (-7.035, 47.583) reference; A3 r 0.5 centre (-8.362, 49.6) between (-7.868, 49.678) and (-8.445, 50.093) reference; A4 r 50.8 centre (0, 0) between (-8.445, 50.093) and (-8.445, -50.093) reference; A5 r 0.5 centre (-8.362, -49.6) between (-8.445, -50.093) and (-7.868, -49.678) reference; A6 r 0.5 centre (-7.108, -48.077) between (-7.035, -47.583) and (-7.602, -47.999) reference; A7 r 48.1 centre (0, 0) between (-7.035, -47.583) and (7.035, -47.583) reference; A8 r 0.5 centre (7.108, -48.077) between (7.602, -47.999) and (7.035, -47.583) reference; A9 r 0.5 centre (8.362, -49.6) between (7.868, -49.678) and (8.445, -50.093) reference; A10 r 50.8 centre (0, 0) between (8.445, -50.093) and (8.445, 50.093) reference; A11 r 0.5 centre (-46.482, 0.5) between (-46.982, 0.508) and (-46.482, 0) reference; A12 r 0.5 centre (-46.475, 0.96) between (-46.459, 1.46) and (-46.975, 0.968) reference; A13 r 0.5 centre (-44.936, 0.912) between (-44.436, 0.904) and (-44.92, 1.412) reference; A14 r 0.5 centre (-44.942, 0.5) between (-44.942, 0) and (-44.442, 0.492) reference; A15 r 0.5 centre (-44.79, 3.732) between (-44.291, 3.692) and (-44.743, 4.229) reference; A16 r 0.5 centre (-44.822, 3.321) between (-44.854, 2.822) and (-44.324, 3.282) reference; A17 r 0.5 centre (-46.359, 3.418) between (-46.857, 3.457) and (-46.39, 2.919) reference; A18 r 0.5 centre (-46.323, 3.877) between (-46.276, 4.374) and (-46.821, 3.916) reference; A19 r 0.5 centre (-44.467, 6.537) between (-43.972, 6.466) and (-44.389, 7.031) reference; A20 r 0.5 centre (-44.525, 6.129) between (-44.588, 5.633) and (-44.03, 6.058) reference; A21 r 0.5 centre (-46.053, 6.322) between (-46.548, 6.392) and (-46.116, 5.826) reference; A22 r 0.5 centre (-45.988, 6.778) between (-45.91, 7.271) and (-46.483, 6.848) reference; A23 r 0.5 centre (-43.969, 9.316) between (-43.479, 9.214) and (-43.86, 9.804) reference; A24 r 0.5 centre (-44.052, 8.912) between (-44.146, 8.421) and (-43.563, 8.811) reference; A25 r 0.5 centre (-45.565, 9.201) between (-46.055, 9.302) and (-45.659, 8.71) reference; A26 r 0.5 centre (-45.472, 9.652) between (-45.363, 10.14) and (-45.961, 9.753) reference; A27 r 0.5 centre (-43.297, 12.058) between (-42.815, 11.926) and (-43.158, 12.538) reference; A28 r 0.5 centre (-43.406, 11.661) between (-43.53, 11.177) and (-42.924, 11.529) reference; A29 r 0.5 centre (-44.897, 12.044) between (-45.38, 12.176) and (-45.022, 11.56) reference; A30 r 0.5 centre (-44.776, 12.488) between (-44.636, 12.968) and (-45.258, 12.62) reference; A31 r 0.5 centre (-42.455, 14.753) between (-41.982, 14.591) and (-42.285, 15.224) reference; A32 r 0.5 centre (-42.588, 14.363) between (-42.743, 13.888) and (-42.115, 14.201) reference; A33 r 0.5 centre (-44.053, 14.839) between (-44.526, 15.001) and (-44.207, 14.364) reference; A34 r 0.5 centre (-43.903, 15.275) between (-43.734, 15.745) and (-44.377, 15.437) reference; A35 r 0.5 centre (-41.444, 17.39) between (-40.983, 17.198) and (-41.246, 17.849) reference; A36 r 0.5 centre (-41.602, 17.009) between (-41.786, 16.544) and (-41.14, 16.818) reference; A37 r 0.5 centre (-43.034, 17.576) between (-43.496, 17.767) and (-43.218, 17.111) reference; A38 r 0.5 centre (-42.858, 18.001) between (-42.659, 18.46) and (-43.32, 18.193) reference; A39 r 0.5 centre (-40.271, 19.958) between (-39.822, 19.738) and (-40.044, 20.403) reference; A40 r 0.5 centre (-40.452, 19.588) between (-40.665, 19.135) and (-40.003, 19.368) reference; A41 r 0.5 centre (-41.845, 20.244) between (-42.294, 20.463) and (-42.058, 19.791) reference; A42 r 0.5 centre (-41.643, 20.657) between (-41.416, 21.102) and (-42.092, 20.877) reference; A43 r 0.5 centre (-38.938, 22.447) between (-38.504, 22.199) and (-38.684, 22.877) reference; A44 r 0.5 centre (-39.142, 22.089) between (-39.383, 21.651) and (-38.708, 21.841) reference; A45 r 0.5 centre (-40.492, 22.831) between (-40.926, 23.079) and (-40.733, 22.393) reference; A46 r 0.5 centre (-40.264, 23.231) between (-40.009, 23.661) and (-40.698, 23.479) reference; A47 r 0.5 centre (-37.452, 24.848) between (-37.034, 24.573) and (-37.171, 25.261) reference; A48 r 0.5 centre (-37.678, 24.503) between (-37.946, 24.081) and (-37.26, 24.229) reference; A49 r 0.5 centre (-38.978, 25.329) between (-39.396, 25.603) and (-39.246, 24.906) reference; A50 r 0.5 centre (-38.725, 25.713) between (-38.444, 26.127) and (-39.143, 25.988) reference; A51 r 0.5 centre (-35.818, 27.15) between (-35.418, 26.85) and (-35.511, 27.545) reference; A52 r 0.5 centre (-36.065, 26.821) between (-36.359, 26.416) and (-35.665, 26.521) reference; A53 r 0.5 centre (-37.311, 27.726) between (-37.711, 28.026) and (-37.605, 27.321) reference; A54 r 0.5 centre (-37.035, 28.094) between (-36.728, 28.489) and (-37.434, 28.394) reference; A55 r 0.5 centre (-34.042, 29.346) between (-33.662, 29.021) and (-33.712, 29.721) reference; A56 r 0.5 centre (-34.31, 29.032) between (-34.629, 28.647) and (-33.93, 28.708) reference; A57 r 0.5 centre (-35.496, 30.014) between (-35.877, 30.339) and (-35.815, 29.629) reference; A58 r 0.5 centre (-35.197, 30.364) between (-34.867, 30.739) and (-35.578, 30.689) reference; A59 r 0.5 centre (-32.132, 31.425) between (-31.773, 31.077) and (-31.779, 31.779) reference; A60 r 0.5 centre (-32.419, 31.13) between (-32.761, 30.765) and (-32.06, 30.782) reference; A61 r 0.5 centre (-33.542, 32.184) between (-33.901, 32.532) and (-33.884, 31.819) reference; A62 r 0.5 centre (-33.221, 32.514) between (-32.868, 32.868) and (-33.58, 32.862) reference; A63 r 0.5 centre (-30.096, 33.381) between (-29.759, 33.011) and (-29.721, 33.712) reference; A64 r 0.5 centre (-30.401, 33.104) between (-30.765, 32.761) and (-30.064, 32.734) reference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; 1 further point
  constraints: 11 point on circle, 10 end point, 4 centre point, 4 coincident, 4 point on line, 2 collinear, 1 vertical, 1 other
  dimensions: "d81" = 2 dimension on C1 A413; "d82" = 1 distance edge to line of A414 L114; "d85" = 72 deg angle of L406 L407 (derived)
extrude "Extrusion15" cut sketch "Sketch11" stored distance "d83" = 0; taper "d84" = 0 deg
fillet "Fillet4" dims "d86" = 2
body "Solid2"
pattern_circular "Circular Pattern1" dims angle "d7" = 360 deg
pattern_circular "Circular Pattern6" dims angle "d74" = 360 deg
node "Reference1"
node "Reference2"
node "Reference3"
node "Reference4"
node "Reference5"
node "Reference6"
node "Reference7"
node "Reference8"
node "Reference9"
node "Reference10"
node "Reference11"
node "Reference12"
node "Reference13"
node "Reference14"
node "Reference15"
node "Reference16"
node "Reference17"
node "Reference18"
node "Reference19"
node "Projected Loop1"
node "Projected Loop2"
node "Projected Loop3"
other parameters: "d12" = 9.66667 (computed from ftube, FOV), "FOV" = 1.5 [user parameter; used in 2 equation terms], "dutycycle" = 4.82359 (computed from holelength, offaxis) [user parameter], "offaxis" = 30 [user parameter; used in 4 equation terms], "angle" = 8.97598 (computed from holediameter, holelength, offaxis) [user parameter; used in 2 equation terms], "holelength" = 45.46127 (computed from dutyratio, offaxis, holediameter) [user parameter; used in 2 equation terms], "holediameter" = 18.53333 (computed from FOV, ftube) [user parameter; used in 3 equation terms], "dutyratio" = 4 [user parameter; used in 1 equation term], "d52" = 45 deg, "minradius" = 0.5 [user parameter]
